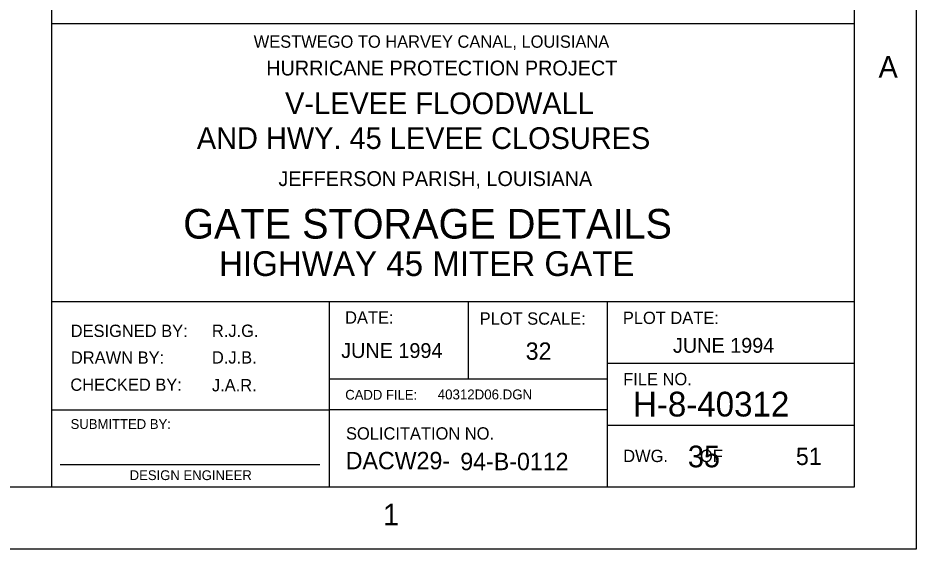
# Model space of a CAD drawing. Extents: x -48 to 108, y -5 to 100.
# Drawn here: x 88.56 to 107.96, y 1.29 to 12.75 of the extents above; entities that cross this region are included whole.
import ezdxf

# ---------------------------------------------------------------- set-up
doc = ezdxf.new("R2010")
doc.units = 0
doc.layers.add('Level 1', color=7, linetype='Continuous')
doc.layers.add('Level 2', color=7, linetype='Continuous')

msp = doc.modelspace()

# ---------------------------------------------------------------- linework, layer by layer
at = {"layer": 'Level 1'}
for p, q in [((89.292, 2.625), (89.292, 15.292)), ((106.625, 12.625), (89.292, 12.625)), ((106.625, 6.625), (89.292, 6.625)), ((95.292, 2.625), (95.292, 6.625)), ((98.292, 4.958), (98.292, 6.625)), ((101.292, 2.625), (101.292, 6.625)), ((106.625, 5.292), (101.292, 5.292)), ((101.292, 4.958), (95.292, 4.958)), ((89.292, 4.292), (95.292, 4.292)), ((101.292, 4.292), (95.292, 4.292)), ((106.625, 3.958), (101.292, 3.958)), ((89.471, 3.114), (95.079, 3.114))]:
    msp.add_line(p, q, dxfattribs=at)
for points in [[(1.292, 75.958), (107.958, 75.958), (107.958, 1.292), (1.292, 1.292)], [(5.292, 74.625), (106.625, 74.625), (106.625, 2.625), (5.292, 2.625)]]:
    msp.add_lwpolyline(points, close=True, dxfattribs=at)

# ---------------------------------------------------------------- texts
for s, height, p in [('A', 0.467, (107.148, 11.461)), ('DATE:', 0.2657, (95.627, 6.155)), ('PLOT SCALE:', 0.26567, (98.533, 6.132)), ('PLOT DATE:', 0.2657, (101.626, 6.147)), ('DESIGNED BY:', 0.26567, (89.7, 5.867)), ('DRAWN BY:', 0.2657, (89.705, 5.289)), ('FILE NO.', 0.2657, (101.634, 4.825)), ('CHECKED BY:', 0.26567, (89.692, 4.705)), ('CADD FILE:', 0.2113, (95.63, 4.514)), ('SUBMITTED BY:', 0.21133, (89.698, 3.883)), ('SOLICITATION NO.', 0.26567, (95.646, 3.653)), ('DACW29-', 0.3743, (95.641, 3.013)), ('DWG.       OF', 0.26567, (101.634, 3.168)), ('DESIGN ENGINEER', 0.21133, (90.974, 2.779)), ('1', 0.467, (96.445, 1.801))]:
    msp.add_text(s, height=height, dxfattribs=at).set_placement(p)
at = {"layer": 'Level 2'}
for s, height, p in [('WESTWEGO TO HARVEY CANAL, LOUISIANA', 0.26567, (93.653, 12.108)), ('HURRICANE PROTECTION PROJECT', 0.32, (93.923, 11.51)), ('V-LEVEE FLOODWALL', 0.46733, (94.331, 10.675)), ('AND HWY. 45 LEVEE CLOSURES', 0.46733, (92.425, 9.924)), ('JEFFERSON PARISH, LOUISIANA', 0.32, (94.186, 9.124)), ('GATE STORAGE DETAILS', 0.63999, (92.13, 7.99)), ('HIGHWAY 45 MITER GATE', 0.53432, (92.904, 7.183)), ('R.J.G.', 0.2657, (92.75, 5.868)), ('JUNE 1994', 0.32, (102.708, 5.526)), ('JUNE 1994', 0.32, (95.542, 5.414)), ('32', 0.3743, (99.527, 5.375)), ('D.J.B.', 0.2657, (92.75, 5.293)), ('J.A.R.', 0.2657, (92.75, 4.693)), ('40312D06.DGN', 0.21432, (97.628, 4.52)), ('H-8-40312', 0.5343, (101.845, 4.151)), ('35', 0.4673, (103.03, 3.055)), ('94-B-0112', 0.3743, (98.115, 2.993)), ('51', 0.3743, (105.364, 3.104))]:
    msp.add_text(s, height=height, dxfattribs=at).set_placement(p)

doc.saveas('drawing.dxf')
